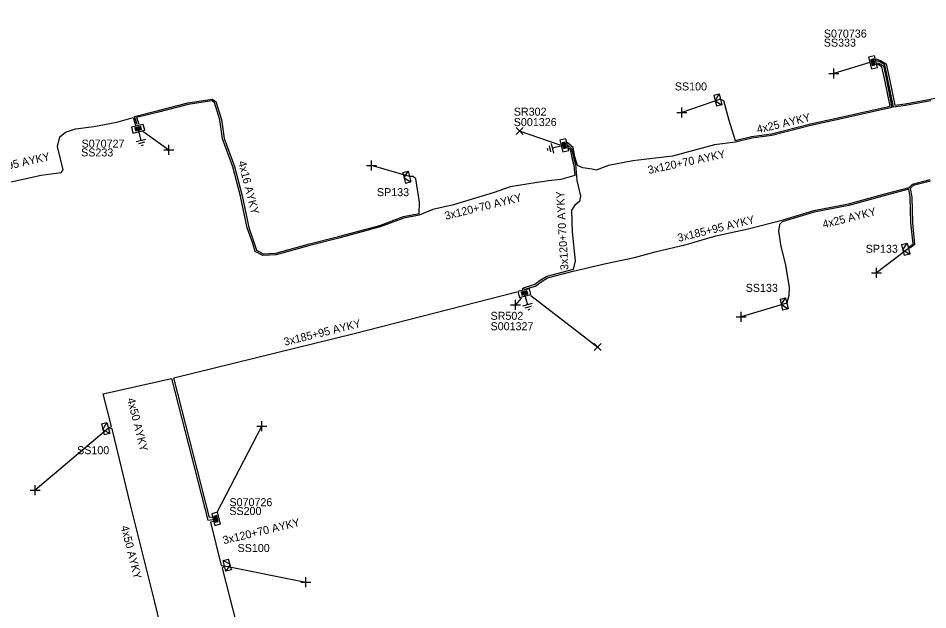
# Model space of a CAD drawing. Extents: x -763093 to -760976, y -1155572 to -1152009.
# Drawn here: x -762286.6 to -762173, y -1154709.7 to -1154635.8 of the extents above; entities that cross this region are included whole.
import ezdxf

# ---------------------------------------------------------------- set-up
doc = ezdxf.new("R2010")
doc.units = 0
for name, color, linetype in [('Vrstva 1', 7, 'Continuous'), ('Vrstva 14', 7, 'Continuous'), ('Vrstva 15', 7, 'Continuous'), ('Vrstva 28', 7, 'Continuous'), ('Vrstva 29', 7, 'Continuous'), ('Vrstva 30', 7, 'Continuous'), ('Vrstva 31', 7, 'Continuous'), ('Vrstva 33', 7, 'Continuous'), ('Vrstva 34', 7, 'Continuous'), ('Vrstva 5', 7, 'Continuous'), ('Vrstva 59', 7, 'Continuous'), ('Vrstva 6', 7, 'Continuous'), ('Vrstva 8', 7, 'Continuous'), ('Vrstva 9', 7, 'Continuous')]:
    doc.layers.add(name, color=color, linetype=linetype)

# ---------------------------------------------------------------- blocks, each defined once
blk = doc.blocks.new('NN800')
at = {"layer": 'Vrstva 1'}
for points in [[(-0.44, 0.44), (0.44, -0.44)], [(-0.44, -0.44), (0.44, 0.44)]]:
    blk.add_lwpolyline(points, dxfattribs=at)
blk = doc.blocks.new('NN620')
at = {"layer": 'Vrstva 8'}
for points in [[(0.75, 0), (-0.75, 0)], [(-0.75, 0), (-0.75, -0.75)], [(0.75, -0.75), (0.75, 0)], [(-0.75, -0.75), (0.75, -0.75)], [(0.37, -0.18), (-0.38, -0.18)], [(-0.38, -0.18), (-0.38, -0.56)], [(-0.38, -0.56), (0.37, -0.56)], [(0.32, -0.23), (-0.33, -0.23)], [(-0.33, -0.23), (-0.33, -0.51)], [(-0.33, -0.51), (0.32, -0.51)], [(0.27, -0.27), (-0.28, -0.27)], [(-0.28, -0.27), (-0.28, -0.46)], [(-0.28, -0.46), (0.27, -0.46)], [(0.23, -0.32), (-0.23, -0.32)], [(-0.23, -0.32), (-0.23, -0.42)], [(-0.23, -0.42), (0.23, -0.42)], [(-0.19, -0.37), (0.19, -0.37)], [(0.23, -0.42), (0.23, -0.32)], [(0.27, -0.46), (0.27, -0.27)], [(0.32, -0.51), (0.32, -0.23)], [(0.37, -0.56), (0.37, -0.18)]]:
    blk.add_lwpolyline(points, dxfattribs=at)
blk = doc.blocks.new('NN630')
at = {"layer": 'Vrstva 9'}
for points in [[(0, -0.7), (-0.7, 0)], [(-0.7, -0.7), (-0.7, 0), (0.7, 0), (0.7, -0.7)], [(-0.7, -0.7), (0.7, -0.7)], [(0, -0.7), (0.7, 0)]]:
    blk.add_lwpolyline(points, dxfattribs=at)
blk = doc.blocks.new('NN810')
at = {"layer": 'Vrstva 14'}
for points in [[(0, -0.64), (0, -1.89)], [(0.63, -1.89), (-0.62, -1.89)], [(0.39, -2.2), (-0.4, -2.2)], [(0, -2.52), (-0.12, -2.52)], [(0.14, -2.52), (0, -2.52)]]:
    blk.add_lwpolyline(points, dxfattribs=at)

msp = doc.modelspace()

# ---------------------------------------------------------------- linework, layer by layer
at = {"layer": 'Vrstva 5'}
for points in [[(-762179.45, -1154640.91), (-762178.86, -1154641.09), (-762178.14, -1154641.52), (-762177.74, -1154643.44), (-762177.07, -1154646.69), (-762175.79, -1154646.52), (-762172.62, -1154645.92), (-762168.63, -1154645.01), (-762165.74, -1154644.32), (-762161.33, -1154642.98), (-762159.22, -1154642.3), (-762158.7, -1154641.76), (-762158.58, -1154640.59), (-762159.53, -1154637.12), (-762159.82, -1154636.77), (-762160.04, -1154636.35), (-762159.69, -1154636.57), (-762159.35, -1154637.02), (-762158.41, -1154640.43), (-762156.63, -1154639.83), (-762152.84, -1154638.95), (-762151.01, -1154638.67), (-762151, -1154637.65), (-762150.98, -1154635.82)], [(-762179.3, -1154641.38), (-762179.02, -1154641.46), (-762178.5, -1154641.77), (-762178.13, -1154643.52), (-762177.43, -1154646.95), (-762179.87, -1154647.52), (-762183.19, -1154648.25), (-762187.57, -1154649.23), (-762192.43, -1154650.45), (-762194.92, -1154650.81), (-762196.98, -1154651.28), (-762199.62, -1154651.65), (-762204.85, -1154653.04), (-762209.81, -1154653.63), (-762212.82, -1154654.2), (-762214.39, -1154654.81), (-762214.87, -1154654.68), (-762216.03, -1154654.49), (-762216.72, -1154654.2), (-762217.04, -1154653.11), (-762217.27, -1154651.96), (-762218, -1154651.34)], [(-762198.85, -1154645.95), (-762198.49, -1154646.1), (-762197.83, -1154648.54), (-762197.03, -1154651.08), (-762194.96, -1154650.61), (-762192.47, -1154650.25), (-762187.61, -1154649.03), (-762183.23, -1154648.05), (-762179.91, -1154647.32), (-762177.66, -1154646.8), (-762178.32, -1154643.56), (-762178.68, -1154641.9), (-762179.1, -1154641.65), (-762179.25, -1154641.6)], [(-762172.58, -1154646.12), (-762175.75, -1154646.72), (-762177.23, -1154646.92), (-762177.93, -1154643.48), (-762178.32, -1154641.65), (-762178.94, -1154641.28), (-762179.36, -1154641.15)], [(-762271.72, -1154649.11), (-762272.04, -1154648.08), (-762269.1, -1154647.36), (-762265.39, -1154646.39), (-762262.34, -1154645.93), (-762261.87, -1154646.21), (-762261.17, -1154648.45), (-762260.86, -1154650.84), (-762259.56, -1154654.33), (-762258.6, -1154657.98), (-762257.77, -1154661.94), (-762257.1, -1154663.89), (-762256.8, -1154664.79), (-762255.98, -1154665.24), (-762254.39, -1154665.16), (-762250.19, -1154663.99), (-762246.58, -1154663.08), (-762241.41, -1154661.69), (-762238.46, -1154660.6), (-762236.49, -1154660.2), (-762236.46, -1154658.78), (-762236.9, -1154655.87), (-762237.22, -1154655.6), (-762237.68, -1154655.59)], [(-762217.82, -1154652.02), (-762217.63, -1154652.18), (-762217.42, -1154653.21), (-762217.15, -1154654.16), (-762217.05, -1154655.48), (-762218.79, -1154655.98), (-762220.34, -1154656.14), (-762221.98, -1154656.37), (-762225.12, -1154656.87), (-762227.13, -1154657.6), (-762232.2, -1154659.11), (-762234.78, -1154659.71), (-762236.47, -1154660.4), (-762238.4, -1154660.8), (-762241.35, -1154661.89), (-762246.52, -1154663.28), (-762250.13, -1154664.19), (-762254.35, -1154665.36), (-762256.02, -1154665.44), (-762256.96, -1154664.93), (-762257.28, -1154663.95), (-762257.97, -1154662), (-762258.8, -1154658.02), (-762259.76, -1154654.39), (-762261.06, -1154650.88), (-762261.37, -1154648.49), (-762262.03, -1154646.35), (-762262.38, -1154646.13), (-762265.35, -1154646.59), (-762269.06, -1154647.56), (-762271.79, -1154648.23), (-762271.52, -1154649.07)], [(-762313.34, -1154659.98), (-762313.5, -1154660.09), (-762313.44, -1154660.66), (-762313.22, -1154660.83), (-762310.04, -1154660.09), (-762307.02, -1154659.7), (-762302.93, -1154658.98), (-762297.49, -1154657.98), (-762294.86, -1154657.51), (-762292.39, -1154657.06), (-762291.54, -1154656.98), (-762287.28, -1154656.21), (-762283.69, -1154655.4), (-762281.21, -1154655.08), (-762280.96, -1154654.76), (-762281.64, -1154651.83), (-762281.38, -1154650.65), (-762280.66, -1154650.04), (-762279.42, -1154649.62), (-762277.12, -1154649.34), (-762274.23, -1154648.79), (-762272.2, -1154648.23), (-762271.91, -1154649.18)], [(-762217.91, -1154651.68), (-762217.45, -1154652.07), (-762217.23, -1154653.16), (-762216.96, -1154654.1), (-762216.8, -1154656.08), (-762216.32, -1154658.03), (-762216.47, -1154658.71), (-762217.06, -1154659.17), (-762217.47, -1154659.79), (-762217.36, -1154662.54), (-762217.02, -1154666.1), (-762217.25, -1154667.2), (-762220.54, -1154668.07), (-762221.38, -1154668.58), (-762222.04, -1154669.09), (-762223.39, -1154669.47), (-762223.61, -1154669.69)], [(-762223.29, -1154669.65), (-762221.94, -1154669.27), (-762221.26, -1154668.74), (-762220.46, -1154668.25), (-762217.24, -1154667.41), (-762213.18, -1154666.44), (-762209.6, -1154665.68), (-762207.01, -1154665.01), (-762203.13, -1154664.08), (-762199.43, -1154663.01), (-762195.39, -1154662.1), (-762191.01, -1154661.01), (-762187.18, -1154659.85), (-762182.87, -1154659), (-762178.16, -1154657.72), (-762175.3, -1154656.97), (-762174.87, -1154656.53), (-762172.66, -1154655.97)], [(-762172.64, -1154656.17), (-762174.77, -1154656.71), (-762175.14, -1154657.09), (-762174.95, -1154658.15), (-762174.86, -1154661.35), (-762174.6, -1154664.09), (-762175.07, -1154664.47), (-762175.38, -1154664.59), (-762175.19, -1154664.31), (-762174.8, -1154664.01), (-762175.06, -1154661.37), (-762175.15, -1154658.17), (-762175.33, -1154657.18), (-762178.1, -1154657.92), (-762182.83, -1154659.2), (-762187.14, -1154660.05), (-762191.14, -1154661.26), (-762191.48, -1154661.59), (-762191.61, -1154662.42), (-762191.3, -1154664.31), (-762190.77, -1154666.44), (-762190.29, -1154669.39), (-762190.3, -1154670.43), (-762190.57, -1154671.42)], [(-762262.3, -1154698.14), (-762262.67, -1154698.18), (-762267.12, -1154680.73), (-762244.6, -1154675.17), (-762224.28, -1154670)], [(-762266.94, -1154720.82), (-762266.61, -1154720.57), (-762269.53, -1154708.55), (-762272.54, -1154696.57), (-762274.83, -1154687.1), (-762275.31, -1154686.99), (-762274.91, -1154686.8), (-762275.94, -1154682.71), (-762267.4, -1154680.81), (-762262.89, -1154698.5), (-762262.23, -1154698.42)], [(-762262.18, -1154698.66), (-762262.53, -1154698.76), (-762261.22, -1154704.16), (-762260.79, -1154704.2), (-762261.11, -1154704.5), (-762254.33, -1154730.82), (-762253.96, -1154730.86), (-762254.25, -1154731.16), (-762251.07, -1154743.75), (-762248.94, -1154752.03), (-762248.56, -1154752.19), (-762248.84, -1154752.46), (-762246.69, -1154761.36), (-762246.19, -1154761.46), (-762246.59, -1154761.73), (-762240.44, -1154784.7), (-762239.02, -1154785.78), (-762237.99, -1154785.84), (-762236.53, -1154785.32), (-762235.21, -1154786.11), (-762234.52, -1154786.06)]]:
    msp.add_lwpolyline(points, dxfattribs=at)
at = {"layer": 'Vrstva 59'}
for points in [[(-762180.19, -1154641.34), (-762184.7, -1154642.74)], [(-762198.85, -1154645.95), (-762203.68, -1154647.58)], [(-762271.02, -1154649.91), (-762267.75, -1154652.27)], [(-762218.88, -1154651.67), (-762223.95, -1154649.91)], [(-762237.68, -1154655.59), (-762242.45, -1154654.21)], [(-762175.38, -1154664.59), (-762179.38, -1154667.6)], [(-762223.75, -1154670.77), (-762224.45, -1154671.62)], [(-762222.54, -1154670.46), (-762214.19, -1154676.88)], [(-762190.57, -1154671.42), (-762196.26, -1154673.09)], [(-762275.31, -1154686.99), (-762284.44, -1154694.75)], [(-762261.72, -1154697.48), (-762256.13, -1154686.75)], [(-762260.79, -1154704.2), (-762250.63, -1154706.25)]]:
    msp.add_lwpolyline(points, dxfattribs=at)

# ---------------------------------------------------------------- block references
at = {"layer": 'Vrstva 15'}
for p, rotation in [((-762271.67, -1154649.26), 13.144866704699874), ((-762217.99, -1154651.61), -76.17681662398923), ((-762223.43, -1154669.78), 14.079111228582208)]:
    msp.add_blockref('NN810', p, dxfattribs=dict(at, rotation=rotation))
at = {"layer": 'Vrstva 28'}
for p, rotation in [((-762179.44, -1154641.23), -75.7533055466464), ((-762271.67, -1154649.26), 13.14486657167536), ((-762217.99, -1154651.61), -76.17681662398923), ((-762223.43, -1154669.78), 14.079111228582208), ((-762262.21, -1154698.42), 104.1821583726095)]:
    msp.add_blockref('NN620', p, dxfattribs=dict(at, rotation=rotation))
at = {"layer": 'Vrstva 31'}
for p, rotation in [((-762198.85, -1154645.95), -75.59103895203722), ((-762237.68, -1154655.59), -75.82193610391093), ((-762175.38, -1154664.59), -76.10398055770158), ((-762190.57, -1154671.42), -76.66143893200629), ((-762275.31, -1154686.99), -76.06159170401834), ((-762260.79, -1154704.2), 104.0362444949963)]:
    msp.add_blockref('NN630', p, dxfattribs=dict(at, rotation=rotation))
at = {"layer": 'Vrstva 34'}
for p, rotation in [((-762184.7, -1154642.74), 45), ((-762203.68, -1154647.58), 45), ((-762267.75, -1154652.27), 45), ((-762242.45, -1154654.21), 45), ((-762179.38, -1154667.6), 45), ((-762224.45, -1154671.62), 45), ((-762196.26, -1154673.09), 45), ((-762256.13, -1154686.75), 45), ((-762284.44, -1154694.75), 44.99999995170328), ((-762250.63, -1154706.25), 45)]:
    msp.add_blockref('NN800', p, dxfattribs=dict(at, rotation=rotation))
for p in [(-762223.95, -1154649.91), (-762214.19, -1154676.88)]:
    msp.add_blockref('NN800', p, dxfattribs=at)

# ---------------------------------------------------------------- texts
at = {"layer": 'Vrstva 29'}
for s, p in [('S070736', (-762185.94, -1154638.24)), ('S001326', (-762224.67, -1154649.29)), ('S070727', (-762278.65, -1154651.98)), ('S001327', (-762227.57, -1154674.78)), ('S070726', (-762260.18, -1154696.75))]:
    msp.add_text(s, height=1, dxfattribs=at).set_placement(p)
at = {"layer": 'Vrstva 30'}
for s, p in [('SS333', (-762185.95, -1154639.37)), ('SR302', (-762224.67, -1154647.99)), ('SS233', (-762278.71, -1154653.08)), ('SR502', (-762227.57, -1154673.48)), ('SS200', (-762260.2, -1154697.85))]:
    msp.add_text(s, height=1, dxfattribs=at).set_placement(p)
at = {"layer": 'Vrstva 33'}
for s, p in [('SS100', (-762204.55, -1154644.84)), ('SP133', (-762241.76, -1154658.04)), ('SP133', (-762180.71, -1154665.11)), ('SS133', (-762195.7, -1154669.99)), ('SS100', (-762279.21, -1154690.26)), ('SS100', (-762259.17, -1154702.47))]:
    msp.add_text(s, height=1, dxfattribs=at).set_placement(p)
at = {"layer": 'Vrstva 6'}
for s, rotation, p in [('4x25 AYKY', 13.355, (-762194.2, -1154650.21)), ('3x185+95 AYKY', 12.867, (-762292.14, -1154655.72)), ('3x120+70 AYKY', 12.101, (-762207.81, -1154655.28)), ('4x16 AYKY', 284.386, (-762259.11, -1154653.77)), ('3x120+70 AYKY', 93.209, (-762217.84, -1154667.24)), ('3x120+70 AYKY', 13.858, (-762233.17, -1154661)), ('4x25 AYKY', 13.896, (-762185.98, -1154662.05)), ('3x185+95 AYKY', 13.836, (-762204.08, -1154663.75)), ('3x185+95 AYKY', 13.869, (-762253.26, -1154676.73)), ('4x50 AYKY', 284.326, (-762272.98, -1154683.36)), ('3x120+70 AYKY', 13.591, (-762260.88, -1154701.51)), ('4x50 AYKY', 284.104, (-762273.76, -1154699.29))]:
    msp.add_text(s, height=1, rotation=rotation, dxfattribs=at).set_placement(p)

doc.saveas('drawing.dxf')
